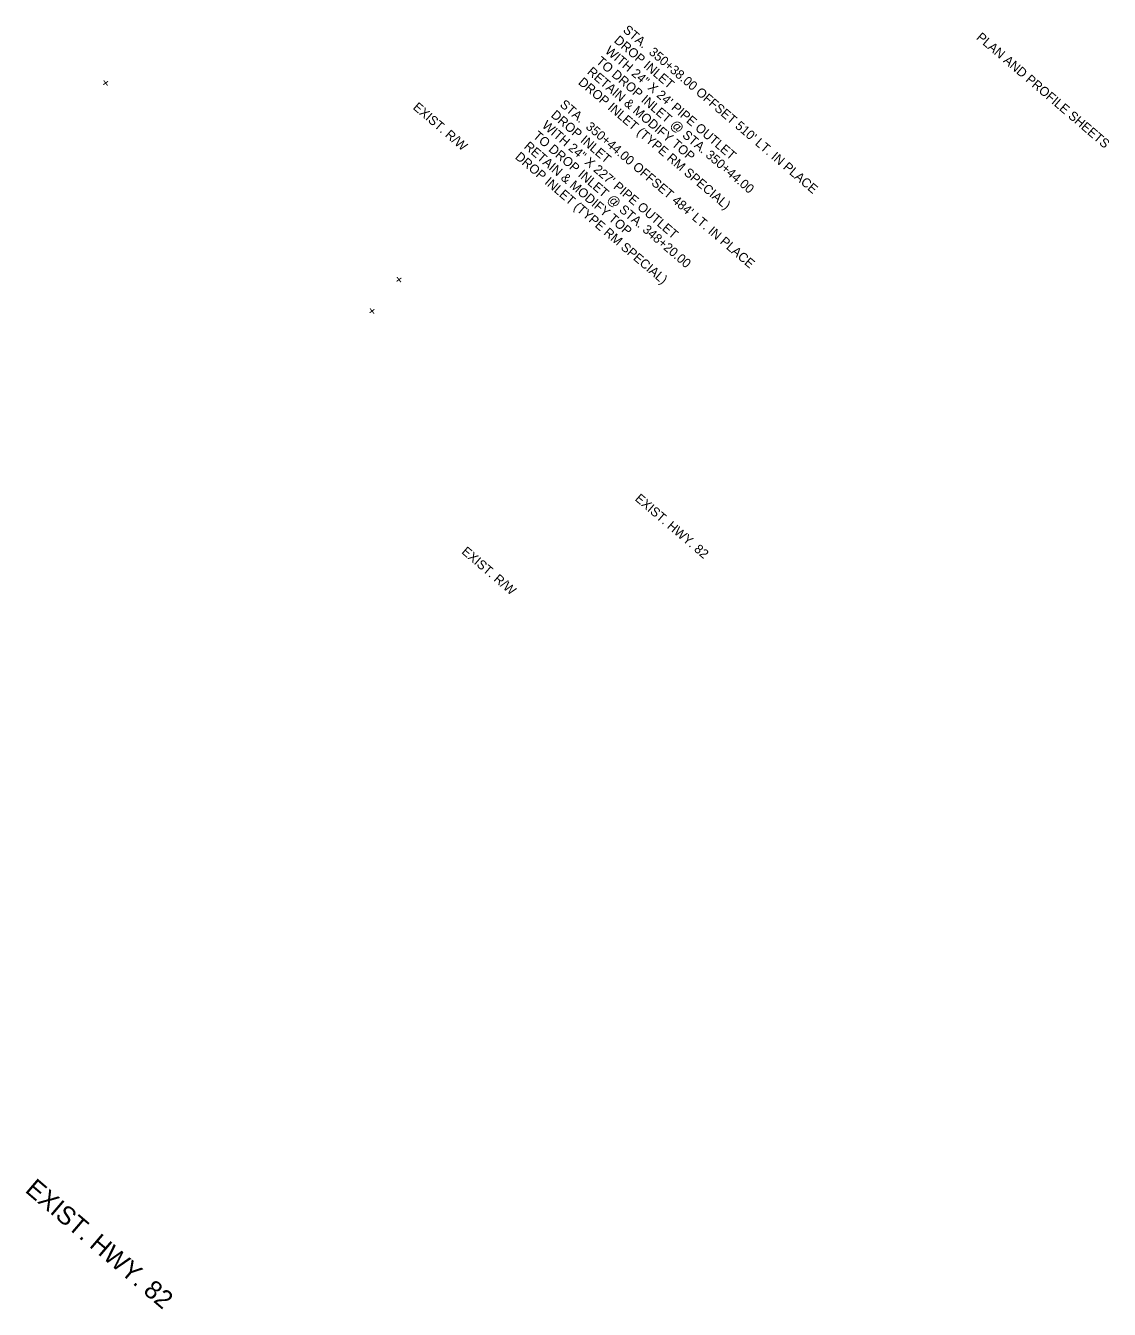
# Model space of a CAD drawing. Extents: x 884041 to 885169, y 1564878 to 1566399.
# Drawn here: x 884460 to 885169, y 1564878 to 1565717 of the extents above; entities that cross this region are included whole.
import ezdxf

# ---------------------------------------------------------------- set-up
doc = ezdxf.new("R2010")
doc.units = 0
for name, color, linetype in [('R_Border', 7, 'Continuous'), ('R_Border Prem', 7, 'Continuous'), ('S_SURVEY_TEXT_ANNOT', 7, 'Continuous')]:
    doc.layers.add(name, color=color, linetype=linetype)

msp = doc.modelspace()

# ---------------------------------------------------------------- texts
at = {"layer": 'R_Border'}
for s, height, rotation, p in [("STA.  350+38.00 OFFSET 510' LT. IN PLACE", 6, 319.43349, (884850.34, 1565713.77)), ('WITH 24" X 24\' PIPE OUTLET', 6, 319.43349, (884838.63, 1565700.09)), ('DROP INLET', 6, 319.43349, (884844.49, 1565706.93)), ('TO DROP INLET @ STA. 350+44.00', 6, 319.43349, (884832.78, 1565693.26)), ('RETAIN & MODIFY TOP', 6, 319.43349, (884826.93, 1565686.42)), ('DROP INLET (TYPE RM SPECIAL)', 6, 319.43349, (884821.08, 1565679.58)), ('EXIST. R/W', 6, 319.43354, (884713.06, 1565663.25)), ('DROP INLET', 6, 319.43349, (884803.24, 1565658.18)), ("STA.  350+44.00 OFFSET 484' LT. IN PLACE", 6, 319.43349, (884809.09, 1565665.02)), ('WITH 24" X 227\' PIPE OUTLET ', 6, 319.43349, (884797.39, 1565651.35)), ('TO DROP INLET @ STA. 348+20.00', 6, 319.43349, (884791.53, 1565644.51)), ('RETAIN & MODIFY TOP', 6, 319.43349, (884785.68, 1565637.67)), ('DROP INLET (TYPE RM SPECIAL)', 6, 319.43349, (884779.83, 1565630.84)), ('EXIST. HWY. 82', 6, 319.43354, (884858.2, 1565407.36)), ('EXIST. R/W', 6, 319.43354, (884744.86, 1565372.75)), ('EXIST. HWY. 82', 12, 319.43349, (884459.33, 1564955.28))]:
    msp.add_text(s, height=height, rotation=rotation, dxfattribs=at).set_placement(p)
at = {"layer": 'R_Border Prem'}
msp.add_text('PLAN AND PROFILE SHEETS', height=6, rotation=319.43349, dxfattribs=at).set_placement((885081.37, 1565708.94))
at = {"layer": 'S_SURVEY_TEXT_ANNOT'}
for p in [(884512.7, 1565683.59), (884704.44, 1565555.04), (884686.85, 1565534.5)]:
    msp.add_text('+', height=6, rotation=217.47218, dxfattribs=at).set_placement(p)

doc.saveas('drawing.dxf')
